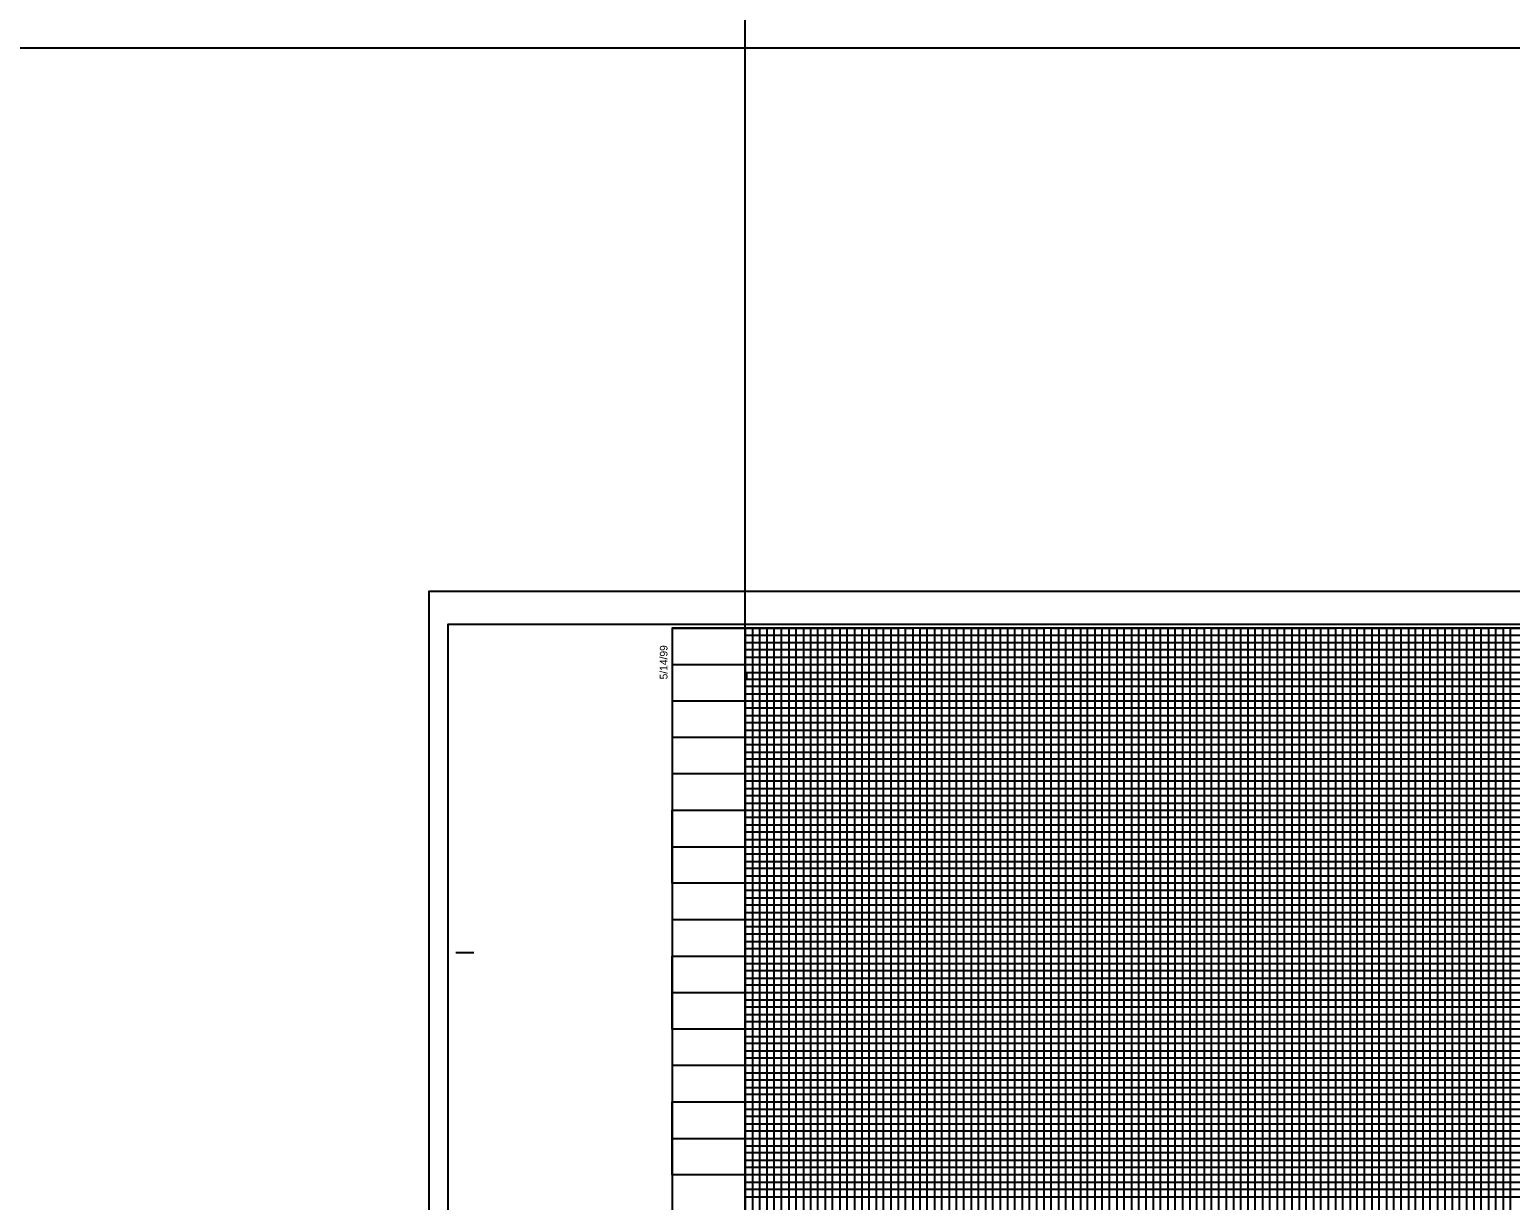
# Model space of a CAD drawing. Extents: x 2345490 to 2445302, y 465165 to 573888.
# Drawn here: x 2381276 to 2382292, y 520153 to 520956 of the extents above; entities that cross this region are included whole.
import ezdxf

# ---------------------------------------------------------------- set-up
doc = ezdxf.new("R2010")
doc.units = 0
for name, color, linetype in [('Old_Level_18', 7, 'Continuous'), ('Old_Level_2', 7, 'Continuous'), ('Old_Level_41', 7, 'Continuous'), ('Old_Level_42', 7, 'Continuous'), ('Old_Level_43', 7, 'Continuous'), ('Old_Level_50', 7, 'Continuous'), ('Old_Level_51', 7, 'Continuous'), ('Old_Level_63', 7, 'Continuous')]:
    doc.layers.add(name, color=color, linetype=linetype)

msp = doc.modelspace()

# ---------------------------------------------------------------- linework, layer by layer
at = {"layer": 'Old_Level_18'}
msp.add_lwpolyline([(2383216.79875, 520545.468), (2381716.79875, 520545.468), (2381716.79875, 519495.468), (2383216.79875, 519495.468)], close=True, dxfattribs=at)
at = {"layer": 'Old_Level_2'}
msp.add_lwpolyline([(2380656.47425, 520943.4165), (2389427.7385, 520943.4165), (2389427.7385, 518326.70625), (2380656.47425, 518326.70625)], close=True, dxfattribs=at)
at = {"layer": 'Old_Level_41'}
msp.add_line((2381568.29875, 520322.968), (2381580.79875, 520322.968), dxfattribs=at)
for points in [[(2381716.79875, 520545.468), (2381766.79875, 520545.468), (2381766.79875, 519520.468), (2381816.79875, 519520.468), (2381816.79875, 520545.468), (2381866.79875, 520545.468), (2381866.79875, 519520.468), (2381916.79875, 519520.468), (2381916.79875, 520545.468), (2381966.79875, 520545.468), (2381966.79875, 519520.468), (2382016.79875, 519520.468), (2382016.79875, 520545.468), (2382066.79875, 520545.468), (2382066.79875, 519520.468), (2382116.79875, 519520.468), (2382116.79875, 520545.468), (2382166.79875, 520545.468), (2382166.79875, 519520.468), (2382216.79875, 519520.468), (2382216.79875, 520545.468), (2382266.79875, 520545.468), (2382266.79875, 519520.468), (2382316.79875, 519520.468)], [(2381791.79875, 519520.468), (2381791.79875, 520545.468), (2381841.79875, 520545.468), (2381841.79875, 519520.468), (2381891.79875, 519520.468), (2381891.79875, 520545.468), (2381941.79875, 520545.468), (2381941.79875, 519520.468), (2381991.79875, 519520.468), (2381991.79875, 520545.468), (2382041.79875, 520545.468), (2382041.79875, 519520.468), (2382091.79875, 519520.468), (2382091.79875, 520545.468), (2382141.79875, 520545.468), (2382141.79875, 519520.468), (2382191.79875, 519520.468), (2382191.79875, 520545.468), (2382241.79875, 520545.468), (2382241.79875, 519520.468), (2382291.79875, 519520.468), (2382291.79875, 520545.468), (2382341.79875, 520545.468)], [(2381716.79875, 520495.468), (2383016.74875, 520495.468)], [(2383016.74875, 520445.468), (2381716.79875, 520445.468), (2381716.79875, 520395.418), (2383216.79875, 520395.418)], [(2383216.79875, 520370.468), (2381716.79875, 520370.468), (2381716.79875, 520420.468), (2383016.74875, 520420.468)], [(2383216.79875, 520345.468), (2381716.79875, 520345.468), (2381716.79875, 520295.468), (2383216.79875, 520295.468)], [(2383216.79875, 520270.468), (2381716.79875, 520270.468), (2381716.79875, 520320.468), (2383216.79875, 520320.468)], [(2383216.79875, 520245.468), (2381716.79875, 520245.468), (2381716.79875, 520195.468), (2383216.79875, 520195.468)]]:
    msp.add_lwpolyline(points, dxfattribs=at)
at = {"layer": 'Old_Level_42'}
for points in [[(2383016.74875, 520470.468), (2381716.89875, 520470.468), (2381716.89875, 520520.418), (2383016.74875, 520520.418)], [(2383216.79875, 520170.468), (2381716.79875, 520170.468), (2381716.79875, 520220.468), (2383216.79875, 520220.468)]]:
    msp.add_lwpolyline(points, dxfattribs=at)
at = {"layer": 'Old_Level_43'}
for p, q in [((2383166.79875, 520365.468), (2381766.79875, 520365.468)), ((2381766.79875, 520365.468), (2381766.79875, 520360.468)), ((2381766.79875, 520360.468), (2383166.79875, 520360.468)), ((2383166.79875, 520340.468), (2381766.79875, 520340.468))]:
    msp.add_line(p, q, dxfattribs=at)
for points in [[(2381771.79875, 520545.468), (2381776.79875, 520545.468), (2381781.79875, 520545.468), (2381786.79875, 520545.468), (2381796.79875, 520545.468), (2381763.74875, 520545.468), (2381768.74875, 520545.468), (2381726.79875, 520545.468), (2381731.79875, 520545.468), (2381736.79875, 520545.468), (2381746.79875, 520545.468), (2381751.79875, 520545.468), (2381756.79875, 520545.468), (2381761.79875, 520545.468), (2381771.79875, 520545.468), (2381771.79875, 519520.468)], [(2383016.74875, 520540.468), (2381766.79875, 520540.468), (2381766.79875, 520535.468), (2383016.74875, 520535.468)], [(2381776.79875, 519520.468), (2381776.79875, 520545.468), (2381781.79875, 520545.468), (2381781.79875, 519520.468)], [(2381786.79875, 519520.468), (2381786.79875, 520545.468), (2381796.79875, 520545.468), (2381796.79875, 519520.468)], [(2381801.79875, 519520.468), (2381801.79875, 520545.468), (2381806.79875, 520545.468), (2381806.79875, 519520.468)], [(2381811.79875, 519520.468), (2381811.79875, 520545.468), (2381821.79875, 520545.468), (2381821.79875, 519520.468)], [(2381826.79875, 519520.468), (2381826.79875, 520545.468), (2381831.79875, 520545.468), (2381831.79875, 519520.468)], [(2381836.79875, 519520.468), (2381836.79875, 520545.468), (2381846.79875, 520545.468), (2381846.79875, 519520.468)], [(2381851.79875, 519520.468), (2381851.79875, 520545.468), (2381856.79875, 520545.468), (2381856.79875, 519520.468)], [(2381861.79875, 519520.468), (2381861.79875, 520545.468), (2381871.79875, 520545.468), (2381871.79875, 519520.468)], [(2381876.79875, 519520.468), (2381876.79875, 520545.468), (2381881.79875, 520545.468), (2381881.79875, 519520.468)], [(2381886.79875, 519520.468), (2381886.79875, 520545.468), (2381896.79875, 520545.468), (2381896.79875, 519520.468)], [(2381901.79875, 519520.468), (2381901.79875, 520545.468), (2381906.79875, 520545.468), (2381906.79875, 519520.468)], [(2381911.79875, 519520.468), (2381911.79875, 520545.468), (2381921.79875, 520545.468), (2381921.79875, 519520.468)], [(2381926.79875, 519520.468), (2381926.79875, 520545.468), (2381931.79875, 520545.468), (2381931.79875, 519520.468)], [(2381936.79875, 519520.468), (2381936.79875, 520545.468), (2381946.79875, 520545.468), (2381946.79875, 519520.468)], [(2381951.79875, 519520.468), (2381951.79875, 520545.468), (2381956.79875, 520545.468), (2381956.79875, 519520.468)], [(2381961.79875, 519520.468), (2381961.79875, 520545.468), (2381971.79875, 520545.468), (2381971.79875, 519520.468)], [(2381976.79875, 519520.468), (2381976.79875, 520545.468), (2381976.79875, 520545.468), (2381981.79875, 520545.468), (2381981.79875, 519520.468)], [(2381986.79875, 519520.468), (2381986.79875, 520545.468), (2381996.79875, 520545.468), (2381996.79875, 519520.468)], [(2382001.79875, 519520.468), (2382001.79875, 520545.468), (2382006.79875, 520545.468), (2382006.79875, 519520.468)], [(2382011.79875, 519520.468), (2382011.79875, 520545.468), (2382021.79875, 520545.468), (2382021.79875, 519520.468)], [(2382026.79875, 519520.468), (2382026.79875, 520545.468), (2382031.79875, 520545.468), (2382031.79875, 519520.468)], [(2382036.79875, 519520.468), (2382036.79875, 520545.468), (2382046.79875, 520545.468), (2382046.79875, 519520.468)], [(2382051.79875, 519520.468), (2382051.79875, 520545.468), (2382056.79875, 520545.468), (2382056.79875, 519520.468)], [(2382061.79875, 519520.468), (2382061.79875, 520545.468), (2382071.79875, 520545.468), (2382071.79875, 519520.468)], [(2382076.79875, 519520.468), (2382076.79875, 520545.468), (2382081.79875, 520545.468), (2382081.79875, 519520.468)], [(2382086.79875, 519520.468), (2382086.79875, 520545.468), (2382096.79875, 520545.468), (2382096.79875, 519520.468)], [(2382101.79875, 520545.468), (2382101.79875, 519520.468), (2382106.79875, 519520.468), (2382106.79875, 520545.468)], [(2382101.79875, 520544.868), (2382101.79875, 519520.468), (2382106.79875, 519520.468), (2382106.79875, 520544.868)], [(2382111.79875, 519520.468), (2382111.79875, 520545.468), (2382121.79875, 520545.468), (2382121.79875, 519520.468)], [(2382126.79875, 519520.468), (2382126.79875, 520545.468), (2382131.79875, 520545.468), (2382131.79875, 519520.468)], [(2382136.79875, 519520.468), (2382136.79875, 520545.468), (2382146.79875, 520545.468), (2382146.79875, 519520.468)], [(2382151.79875, 519520.468), (2382151.79875, 520545.468), (2382156.79875, 520545.468), (2382156.79875, 519520.468)], [(2382161.79875, 519520.468), (2382161.79875, 520545.468), (2382171.79875, 520545.468), (2382171.79875, 519520.468)], [(2382176.79875, 519520.468), (2382176.79875, 520545.468), (2382181.79875, 520545.468), (2382181.79875, 519520.468)], [(2382186.79875, 519520.468), (2382186.79875, 520545.468), (2382196.79875, 520545.468), (2382196.79875, 519520.468)], [(2382201.79875, 519520.468), (2382201.79875, 520545.468), (2382206.79875, 520545.468), (2382206.79875, 519520.468)], [(2382211.79875, 519520.468), (2382211.79875, 520545.468), (2382221.79875, 520545.468), (2382221.79875, 519520.468)], [(2382226.79875, 519520.468), (2382226.79875, 520545.468), (2382231.79875, 520545.468), (2382231.79875, 519520.468)], [(2382236.79875, 519520.468), (2382236.79875, 520545.468), (2382246.79875, 520545.468), (2382246.79875, 519520.468)], [(2382251.79875, 520545.468), (2382251.79875, 519520.468), (2382256.79875, 519520.468), (2382256.79875, 520545.468), (2382261.79875, 520545.468), (2382261.79875, 519520.468), (2382271.79875, 519520.468), (2382271.79875, 520545.468), (2382276.79875, 520545.468), (2382276.79875, 519520.468), (2382281.79875, 519520.468), (2382281.79875, 520545.468), (2382286.79875, 520545.468), (2382286.79875, 519520.468)], [(2383016.74875, 520530.468), (2381766.79875, 520530.468), (2381766.79875, 520525.468), (2383016.74875, 520525.468)], [(2383016.74875, 520514.718), (2381767.79875, 520514.718), (2381767.79875, 520510.468), (2383016.74875, 520510.468)], [(2383016.74875, 520505.468), (2381766.79875, 520505.468), (2381766.79875, 520500.468), (2383016.74875, 520500.468)], [(2383016.74875, 520490.468), (2381766.79875, 520490.468), (2381766.79875, 520485.468), (2383016.74875, 520485.468)], [(2383016.74875, 520480.468), (2381766.79875, 520480.468), (2381766.79875, 520475.468), (2383016.74875, 520475.468)], [(2383016.74875, 520465.468), (2381766.79875, 520465.468), (2381766.79875, 520460.468), (2383016.74875, 520460.468)], [(2383016.74875, 520455.468), (2381766.79875, 520455.468), (2381766.79875, 520450.468), (2383016.74875, 520450.468)], [(2383016.74875, 520440.468), (2381766.79875, 520440.468), (2381766.79875, 520435.468), (2383016.74875, 520435.468)], [(2383016.74875, 520430.468), (2381766.79875, 520430.468), (2381766.79875, 520425.468), (2383016.74875, 520425.468)], [(2383016.74875, 520415.468), (2381766.79875, 520415.468), (2381766.79875, 520410.468), (2383016.74875, 520410.468)], [(2383166.79875, 520405.468), (2381766.79875, 520405.468), (2381766.79875, 520405.468), (2381766.79875, 520385.468), (2383166.79875, 520385.468)], [(2381766.79875, 520400.468), (2383166.79875, 520400.468)], [(2383166.79875, 520390.468), (2381766.79875, 520390.468)], [(2383166.79875, 520380.468), (2381766.79875, 520380.468), (2381766.79875, 520375.468), (2383166.79875, 520375.468)], [(2383166.79875, 520355.468), (2381766.79875, 520355.468), (2381766.79875, 520350.468), (2383166.79875, 520350.468)], [(2383166.79875, 520335.468), (2381766.79875, 520335.468), (2381766.79875, 520330.468), (2383166.79875, 520330.468)], [(2383166.79875, 520325.468), (2381766.79875, 520325.468)], [(2381766.79875, 520315.468), (2383166.79875, 520315.468)], [(2383166.79875, 520310.468), (2381766.79875, 520310.468), (2381766.79875, 520305.468), (2383166.79875, 520305.468)], [(2383166.79875, 520300.468), (2381766.79875, 520300.468), (2381766.79875, 520290.468), (2383166.79875, 520290.468)], [(2383166.79875, 520285.468), (2381766.79875, 520285.468), (2381766.79875, 520280.468), (2383166.79875, 520280.468)], [(2383166.79875, 520275.468), (2381766.79875, 520275.468), (2381766.79875, 520265.468), (2383166.79875, 520265.468)], [(2383166.79875, 520260.468), (2381766.79875, 520260.468), (2381766.79875, 520255.468), (2383166.79875, 520255.468)], [(2383166.79875, 520250.468), (2381766.79875, 520250.468), (2381766.79875, 520240.468), (2383166.79875, 520240.468)], [(2383166.79875, 520235.468), (2381766.79875, 520235.468), (2381766.79875, 520230.468), (2383166.79875, 520230.468)], [(2383166.79875, 520225.468), (2381766.79875, 520225.468), (2381766.79875, 520215.468), (2383166.79875, 520215.468)], [(2383166.79875, 520210.468), (2381766.79875, 520210.468), (2381766.79875, 520205.468), (2383166.79875, 520205.468)], [(2383166.79875, 520200.468), (2381766.79875, 520200.468), (2381766.79875, 520190.468), (2383166.79875, 520190.468)], [(2383166.79875, 520185.468), (2381766.79875, 520185.468), (2381766.79875, 520180.468), (2383166.79875, 520180.468)], [(2383166.79875, 520175.468), (2381766.79875, 520175.468), (2381766.79875, 520165.468), (2383166.79875, 520165.468)], [(2383166.79875, 520160.468), (2381766.79875, 520160.468), (2381766.79875, 520155.468), (2383166.79875, 520155.468)]]:
    msp.add_lwpolyline(points, dxfattribs=at)
at = {"layer": 'Old_Level_50'}
msp.add_lwpolyline([(2383229.29875, 520548.018), (2381562.79875, 520548.018), (2381562.79875, 519492.918), (2383229.29875, 519492.918)], close=True, dxfattribs=at)
at = {"layer": 'Old_Level_51'}
msp.add_lwpolyline([(2383233.79875, 520570.468), (2381549.79875, 520570.468), (2381549.79875, 519470.468), (2383233.79875, 519470.468)], close=True, dxfattribs=at)
at = {"layer": 'Old_Level_63'}
msp.add_line((2381766.79875, 519520.468), (2381766.79875, 522020.468), dxfattribs=at)

# ---------------------------------------------------------------- texts
at = {"layer": 'Old_Level_41'}
msp.add_text('5/14/99', height=5.25, rotation=90, dxfattribs=at).set_placement((2381713.54875, 520510.268))

doc.saveas('drawing.dxf')
